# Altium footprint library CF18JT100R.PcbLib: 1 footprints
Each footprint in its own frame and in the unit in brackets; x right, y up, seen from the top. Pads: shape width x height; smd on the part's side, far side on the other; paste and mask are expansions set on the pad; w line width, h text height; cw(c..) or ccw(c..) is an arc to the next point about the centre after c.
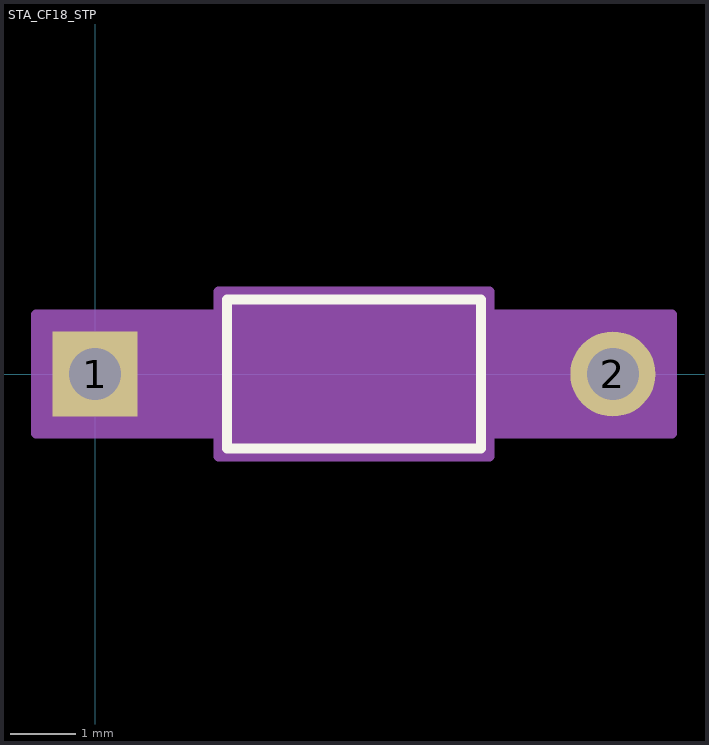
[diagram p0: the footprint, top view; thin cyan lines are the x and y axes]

## STA_CF18_STP [mil]
pads (2):
  rect 51x51 hole 31 paste-25.5 mask+0: 1(0,0)
  round 51 hole 31 paste-25.5 mask+0: 2(310,0)
Top Overlay:
  lines w6: 79,-44.5 231,-44.5 231,44.5 79,44.5 79,-44.5
  text ".Designator" at 17.5,-25 h50
Mechanical 13:
  lines w1: 0,0 84,0 ; 226,0 310,0 ; 84,-39.5 226,-39.5 226,39.5 84,39.5 84,-39.5
  text ".Designator" at 17.5,-25 h50
Mechanical 15:
  region: 74,-35.5 -35.5,-35.5 -35.5,35.5 74,35.5 74,49.5 236,49.5 236,35.5 345.5,35.5 345.5,-35.5 236,-35.5 236,-49.5 74,-49.5
  lines w6: -35.5,-35.5 -35.5,35.5 74,35.5 74,49.5 236,49.5 236,35.5 345.5,35.5 345.5,-35.5 236,-35.5 236,-49.5 74,-49.5 74,-35.5 -35.5,-35.5
3D body "STA_CF18_STP.step": height 78.99, standoff -110, extent -10.51,-39.21 320.51,39.21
